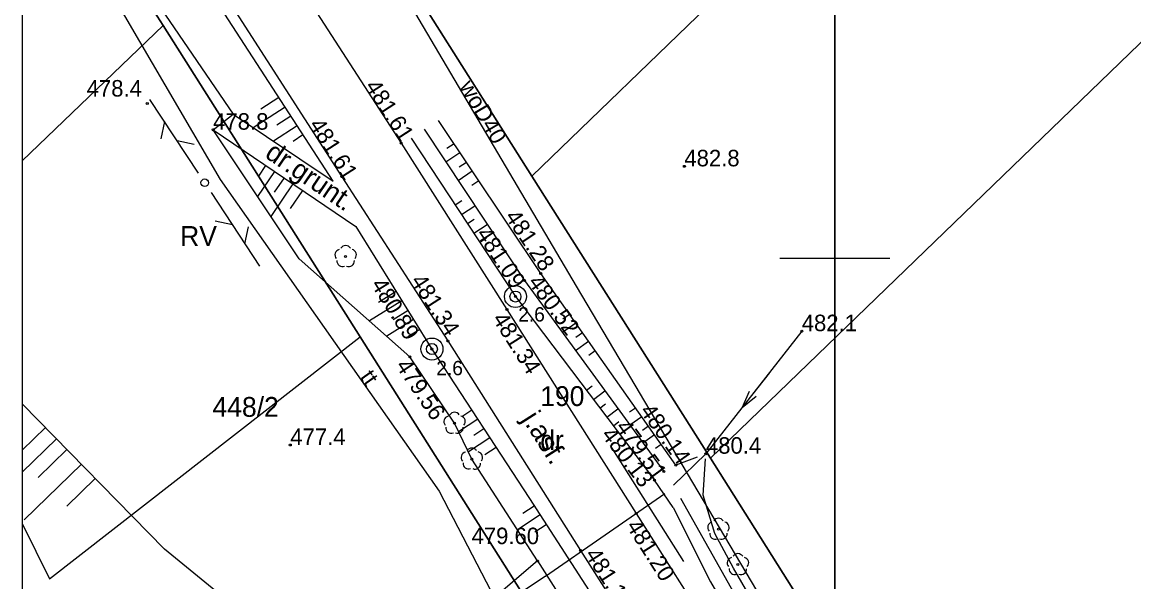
# Model space of a CAD drawing. Extents: x 4650326 to 4650741, y 5341000 to 5341288.
# Drawn here: x 4650326.2 to 4650427.1, y 5341070.6 to 5341121.4 of the extents above; entities that cross this region are included whole.
import ezdxf

# ---------------------------------------------------------------- set-up
doc = ezdxf.new("R2010")
doc.units = 0
for name, color, linetype in [('Warstwa 20', 7, 'Continuous'), ('Warstwa 24', 7, 'Continuous'), ('Warstwa 25', 7, 'Continuous'), ('Warstwa 26', 7, 'Continuous'), ('Warstwa 27', 7, 'Continuous'), ('Warstwa 35', 7, 'Continuous'), ('Warstwa 38', 7, 'Continuous'), ('Warstwa 41', 7, 'Continuous'), ('Warstwa 45', 7, 'Continuous'), ('Warstwa 46', 7, 'Continuous'), ('Warstwa 48', 7, 'Continuous'), ('Warstwa 50', 7, 'Continuous'), ('Warstwa 53', 7, 'Continuous'), ('Warstwa 60', 7, 'Continuous'), ('Warstwa 9', 7, 'Continuous')]:
    doc.layers.add(name, color=color, linetype=linetype)

msp = doc.modelspace()

# ---------------------------------------------------------------- linework, layer by layer
at = {"layer": 'Warstwa 20'}
msp.add_lwpolyline([(4650356.17, 5341132), (4650376.51, 5341097.46), (4650399.08, 5341059.32), (4650417.65, 5341028.07), (4650427.373, 5341012.003)], dxfattribs=at)
at = {"layer": 'Warstwa 25'}
for p, q in [((4650476.09, 5341207.62), (4650372.48, 5341107.47)), ((4650490.79, 5341180.52), (4650388.7, 5341081.84)), ((4650338.98, 5341121.15), (4650326.19, 5341141.38)), ((4650338.98, 5341121.15), (4650326.19, 5341141.38)), ((4650372.48, 5341107.47), (4650354.27, 5341136.26)), ((4650372.48, 5341107.47), (4650354.27, 5341136.26)), ((4650338.98, 5341121.15), (4650326.19, 5341108.843)), ((4650356.87, 5341092.87), (4650338.98, 5341121.15)), ((4650356.87, 5341092.87), (4650338.98, 5341121.15)), ((4650388.7, 5341081.84), (4650372.48, 5341107.47)), ((4650388.7, 5341081.84), (4650372.48, 5341107.47)), ((4650372.55, 5341068.08), (4650356.87, 5341092.87)), ((4650372.55, 5341068.08), (4650356.87, 5341092.87)), ((4650390.3, 5341079.3), (4650388.7, 5341081.84)), ((4650390.3, 5341079.3), (4650388.7, 5341081.84)), ((4650406.56, 5341053.51), (4650390.3, 5341079.3)), ((4650406.56, 5341053.51), (4650390.3, 5341079.3))]:
    msp.add_line(p, q, dxfattribs=at)
msp.add_lwpolyline([(4650326.19, 5341136.061), (4650331.83, 5341128.32), (4650344.18, 5341107.15), (4650364.07, 5341078.82), (4650371.33, 5341064.82), (4650381.68, 5341051.41)], dxfattribs=at)
at = {"layer": 'Warstwa 27'}
for p, q in [((4650326.19, 5341141.38), (4650338.98, 5341121.15)), ((4650326.19, 5341141.38), (4650338.98, 5341121.15)), ((4650354.27, 5341136.26), (4650372.48, 5341107.47)), ((4650354.27, 5341136.26), (4650372.48, 5341107.47)), ((4650338.98, 5341121.15), (4650356.87, 5341092.87)), ((4650338.98, 5341121.15), (4650356.87, 5341092.87)), ((4650372.48, 5341107.47), (4650388.7, 5341081.84)), ((4650372.48, 5341107.47), (4650388.7, 5341081.84)), ((4650328.68, 5341070.86), (4650356.87, 5341092.87)), ((4650356.87, 5341092.87), (4650372.55, 5341068.08)), ((4650356.87, 5341092.87), (4650372.55, 5341068.08)), ((4650388.7, 5341081.84), (4650390.3, 5341079.3)), ((4650388.7, 5341081.84), (4650390.3, 5341079.3)), ((4650390.3, 5341079.3), (4650406.56, 5341053.51)), ((4650390.3, 5341079.3), (4650406.56, 5341053.51)), ((4650326.19, 5341075.895), (4650328.68, 5341070.86))]:
    msp.add_line(p, q, dxfattribs=at)
at = {"layer": 'Warstwa 35'}
for p, q in [((4650343.53, 5341111.68), (4650345.35, 5341113.08)), ((4650379.6, 5341082.97), (4650386.24, 5341072.45)), ((4650385.31, 5341077.34), (4650383.62, 5341079.83)), ((4650373.71, 5341071.11), (4650384.57, 5341078.62)), ((4650372.25, 5341078.17), (4650379.35, 5341067.21)), ((4650372.99, 5341072.49), (4650374.64, 5341069.94))]:
    msp.add_line(p, q, dxfattribs=at)
for points in [[(4650340.68, 5341141.28), (4650360.61, 5341110.45), (4650370.22, 5341095.34), (4650381.95, 5341076.81), (4650396.56, 5341053.79), (4650422.67, 5341012.73), (4650423.136, 5341012.003)], [(4650335.36, 5341138.28), (4650345.04, 5341123.21), (4650355.21, 5341107.41), (4650364.84, 5341092.48), (4650376.91, 5341073.44), (4650391.69, 5341050.19), (4650398.26, 5341039.76), (4650401.18, 5341035.09), (4650415.921, 5341012.003)], [(4650354.42, 5341106.99), (4650344.2, 5341122.78), (4650334.38, 5341137.96)]]:
    msp.add_lwpolyline(points, dxfattribs=at)
for centre, radius in [((4650370.99, 5341096.52), 1), ((4650370.99, 5341096.52), 0.5), ((4650363.4, 5341091.75), 1), ((4650363.4, 5341091.75), 0.5)]:
    msp.add_circle(centre, radius, dxfattribs=at)
at = {"layer": 'Warstwa 38'}
msp.add_circle((4650342.77, 5341106.86), 0.35, dxfattribs=at)
at = {"layer": 'Warstwa 41'}
for centre in [(4650355.56, 5341100.15), (4650365.45, 5341085.01), (4650367.02, 5341081.75), (4650389.42, 5341075.38), (4650391.19, 5341072.16)]:
    msp.add_circle(centre, 0.09, dxfattribs=at)
for centre, start, end in [((4650355.567, 5341100.65), 30.76957, 149.23063), ((4650355.091, 5341100.302), 103.05194, 221.33515), ((4650356.042, 5341100.307), 318.93901, 77.55513), ((4650355.268, 5341099.749), 174.17267, 292.61566), ((4650355.856, 5341099.742), 246.13103, 4.5225), ((4650365.457, 5341085.51), 30.76957, 149.23063), ((4650364.981, 5341085.162), 103.05194, 221.33515), ((4650365.158, 5341084.609), 174.17267, 292.61566), ((4650365.932, 5341085.167), 318.93901, 77.55513), ((4650365.746, 5341084.602), 246.13103, 4.5225), ((4650367.027, 5341082.25), 30.76957, 149.23063), ((4650366.551, 5341081.902), 103.05194, 221.33515), ((4650367.502, 5341081.907), 318.93901, 77.55513), ((4650366.728, 5341081.349), 174.17267, 292.61566), ((4650367.316, 5341081.342), 246.13103, 4.5225), ((4650388.951, 5341075.532), 103.05194, 221.33515), ((4650389.427, 5341075.88), 30.76957, 149.23063), ((4650389.902, 5341075.537), 318.93901, 77.55513), ((4650389.128, 5341074.979), 174.17267, 292.61566), ((4650389.716, 5341074.972), 246.13103, 4.5225), ((4650390.721, 5341072.312), 103.05194, 221.33515), ((4650391.197, 5341072.66), 30.76957, 149.23063), ((4650391.672, 5341072.317), 318.93901, 77.55513), ((4650390.898, 5341071.759), 174.17267, 292.61566), ((4650391.486, 5341071.752), 246.13103, 4.5225)]:
    msp.add_arc(centre, 0.5, start, end, dxfattribs=at)
at = {"layer": 'Warstwa 45'}
for centre in [(4650337.55, 5341114.07), (4650343.53, 5341111.68), (4650360.61, 5341110.45), (4650386.33, 5341108.35), (4650355.21, 5341107.41), (4650371.8, 5341097.97), (4650373.28, 5341098.61), (4650370.99, 5341096.52), (4650370.22, 5341095.34), (4650396.99, 5341093.37), (4650363.4, 5341091.75), (4650364.84, 5341092.48), (4650361.4, 5341091.05), (4650350.54, 5341083.03), (4650388.29, 5341082.24), (4650384.47, 5341080.61), (4650385.56, 5341081.19), (4650383.62, 5341079.83), (4650381.95, 5341076.81), (4650372.99, 5341072.49), (4650376.91, 5341073.44)]:
    msp.add_circle(centre, 0.09, dxfattribs=at)
at = {"layer": 'Warstwa 46'}
for p, q in [((4650342.192, 5341107.737), (4650337.792, 5341114.418)), ((4650339.112, 5341112.414), (4650338.79, 5341110.847)), ((4650340.25, 5341110.686), (4650341.817, 5341110.363)), ((4650343.345, 5341105.982), (4650347.728, 5341099.289)), ((4650345.28, 5341103.028), (4650343.714, 5341103.354)), ((4650346.413, 5341101.297), (4650346.74, 5341102.862))]:
    msp.add_line(p, q, dxfattribs=at)
at = {"layer": 'Warstwa 48'}
for points in [[(4650326.19, 5341000.203), (4650737.19, 5341000.203), (4650737.19, 5341288.203), (4650326.19, 5341288.203)], [(4650326.19, 5341012.003), (4650737.19, 5341012.003), (4650737.19, 5341261.537), (4650326.19, 5341261.537)]]:
    msp.add_lwpolyline(points, close=True, dxfattribs=at)
at = {"layer": 'Warstwa 50'}
for p, q in [((4650349.49, 5341114.6), (4650347.86, 5341113.55)), ((4650350.06, 5341113.72), (4650347.18, 5341111.85)), ((4650351.16, 5341112.02), (4650349.01, 5341110.63)), ((4650350.59, 5341112.9), (4650349.33, 5341112.08)), ((4650351.69, 5341111.21), (4650350.79, 5341110.62)), ((4650365.41, 5341110.39), (4650364.77, 5341109.97)), ((4650365.95, 5341109.58), (4650364.68, 5341108.73)), ((4650349.11, 5341107.89), (4650347.56, 5341105.62)), ((4650348.3, 5341108.44), (4650347.64, 5341107.47)), ((4650367.07, 5341107.9), (4650365.8, 5341107.04)), ((4650366.53, 5341108.71), (4650365.89, 5341108.28)), ((4650349.97, 5341107.3), (4650349.08, 5341105.99)), ((4650367.66, 5341107.02), (4650367.02, 5341106.6)), ((4650350.78, 5341106.75), (4650348.77, 5341103.8)), ((4650351.65, 5341106.16), (4650350.52, 5341104.51)), ((4650365.51, 5341104.84), (4650366.12, 5341105.24)), ((4650366.09, 5341103.96), (4650367.31, 5341104.76)), ((4650366.63, 5341103.15), (4650367.23, 5341103.55)), ((4650367.2, 5341102.27), (4650368.42, 5341103.07)), ((4650367.74, 5341101.46), (4650368.35, 5341101.86)), ((4650360.16, 5341096.97), (4650358.56, 5341095.97)), ((4650360.67, 5341096.14), (4650357.72, 5341094.3)), ((4650361.23, 5341095.25), (4650359.88, 5341094.41)), ((4650375.91, 5341094.88), (4650375.3, 5341094.45)), ((4650361.74, 5341094.42), (4650359.3, 5341092.91)), ((4650376.47, 5341094.09), (4650375.26, 5341093.24)), ((4650362.29, 5341093.53), (4650361.21, 5341092.86)), ((4650377.07, 5341093.23), (4650376.48, 5341092.81)), ((4650377.63, 5341092.44), (4650376.45, 5341091.6)), ((4650378.24, 5341091.58), (4650377.65, 5341091.17)), ((4650377.44, 5341088), (4650377.97, 5341088.4)), ((4650378.07, 5341087.16), (4650379.11, 5341087.95)), ((4650378.66, 5341086.39), (4650379.17, 5341086.78)), ((4650367.03, 5341086.18), (4650366.21, 5341085.65)), ((4650379.29, 5341085.55), (4650380.3, 5341086.32)), ((4650381.9, 5341086.39), (4650381.35, 5341086)), ((4650367.56, 5341085.37), (4650365.82, 5341084.24)), ((4650379.88, 5341084.78), (4650380.38, 5341085.16)), ((4650382.46, 5341085.59), (4650381.38, 5341084.83)), ((4650383.06, 5341084.74), (4650382.53, 5341084.36)), ((4650328.31, 5341084.61), (4650326.19, 5341082.546)), ((4650368.66, 5341083.68), (4650366.71, 5341082.4)), ((4650368.13, 5341084.49), (4650367.21, 5341083.89)), ((4650383.62, 5341083.94), (4650382.57, 5341083.2)), ((4650329.3, 5341083.59), (4650326.19, 5341080.551)), ((4650369.23, 5341082.8), (4650368.22, 5341082.14)), ((4650384.22, 5341083.09), (4650383.7, 5341082.72)), ((4650330.25, 5341082.63), (4650327.63, 5341080.07)), ((4650331.56, 5341081.29), (4650326.37, 5341076.22)), ((4650332.81, 5341080), (4650330.24, 5341077.48)), ((4650373.22, 5341076.67), (4650371.16, 5341075.33)), ((4650372.7, 5341077.48), (4650371.67, 5341076.81)), ((4650373.79, 5341075.79), (4650372.76, 5341075.12))]:
    msp.add_line(p, q, dxfattribs=at)
for points in [[(4650326.19, 5341140.814), (4650334.23, 5341129.37), (4650345.35, 5341113.08), (4650354.42, 5341106.99)], [(4650387.49, 5341081.93), (4650385.56, 5341081.19), (4650373.28, 5341098.61), (4650363.99, 5341112.51)], [(4650343.53, 5341111.68), (4650356.48, 5341102.88), (4650363.4, 5341091.75), (4650372.25, 5341078.17)], [(4650372.99, 5341072.49), (4650367.02, 5341081.75), (4650365.45, 5341085.01), (4650361.4, 5341091.05), (4650351.34, 5341099.93), (4650343.53, 5341111.68)], [(4650362.69, 5341111.74), (4650371.8, 5341097.97), (4650384.47, 5341080.61)], [(4650361.52, 5341110.9), (4650370.99, 5341096.52), (4650383.62, 5341079.83)], [(4650372.99, 5341072.49), (4650368.82, 5341068.93), (4650361.34, 5341066.45), (4650355.07, 5341066.65), (4650350.09, 5341064.57), (4650339.1, 5341073.56), (4650326.19, 5341086.778)], [(4650406.82, 5341060.31), (4650400.86, 5341058.99), (4650397.53, 5341060.28), (4650390.8, 5341071.85), (4650389.11, 5341074.99), (4650388.04, 5341078.47), (4650388.26, 5341081.77)], [(4650407.19, 5341059.34), (4650400.92, 5341057.96), (4650396.57, 5341059.4), (4650386.02, 5341078.18)], [(4650385.31, 5341077.34), (4650388.71, 5341070.59), (4650395.77, 5341058.4), (4650400.94, 5341056.54), (4650407.35, 5341058.52)]]:
    msp.add_lwpolyline(points, dxfattribs=at)
at = {"layer": 'Warstwa 53'}
msp.add_line((4650373.71, 5341071.11), (4650369.41, 5341068.23), dxfattribs=at)
msp.add_lwpolyline([(4650396.99, 5341093.37), (4650388.29, 5341082.24), (4650385.35, 5341079.38)], dxfattribs=at)
at = {"layer": 'Warstwa 60'}
for p, q in [((4650400, 5341012.003), (4650400, 5341261.537)), ((4650400, 5341261.537), (4650400, 5341012.003)), ((4650400, 5341095), (4650400, 5341105)), ((4650400, 5341095), (4650400, 5341105)), ((4650400, 5341095), (4650400, 5341105)), ((4650395, 5341100), (4650400, 5341100)), ((4650395, 5341100), (4650405, 5341100)), ((4650400, 5341100), (4650405, 5341100))]:
    msp.add_line(p, q, dxfattribs=at)
at = {"layer": 'Warstwa 9'}
for p, q in [((4650394.02, 5341089.57), (4650392.548, 5341087.674)), ((4650391.567, 5341086.41), (4650392.232, 5341087.919)), ((4650392.864, 5341087.429), (4650391.567, 5341086.41))]:
    msp.add_line(p, q, dxfattribs=at)

# ---------------------------------------------------------------- texts
at = {"layer": 'Warstwa 20'}
msp.add_text('woD40', height=1.5, rotation=300.48745, dxfattribs=at).set_placement((4650365.82, 5341115.61))
at = {"layer": 'Warstwa 24'}
for s, p in [('190', (4650373.24, 5341086.57)), ('448/2', (4650343.47, 5341085.59))]:
    msp.add_text(s, height=1.8, dxfattribs=at).set_placement(p)
at = {"layer": 'Warstwa 25'}
msp.add_text('tt', height=1.5, rotation=305.07226, dxfattribs=at).set_placement((4650356.79, 5341089.19))
at = {"layer": 'Warstwa 26'}
for s, p in [('RV', (4650340.53, 5341101.12)), ('dr', (4650373.24, 5341082.57))]:
    msp.add_text(s, height=1.8, dxfattribs=at).set_placement(p)
at = {"layer": 'Warstwa 35'}
for s, rotation, p in [('dr.grunt.', 325.80244, (4650348.13, 5341109.23)), ('j.asf.', 302.37191, (4650371.54, 5341085.39))]:
    msp.add_text(s, height=1.8, rotation=rotation, dxfattribs=at).set_placement(p)
for p in [(4650371.24, 5341094.25), (4650363.8, 5341089.37)]:
    msp.add_text('2.6', height=1.3, dxfattribs=at).set_placement(p)
at = {"layer": 'Warstwa 45'}
for s, p in [('478.4', (4650332.04, 5341114.69)), ('478.8', (4650343.53, 5341111.68)), ('482.8', (4650386.33, 5341108.35)), ('482.1', (4650396.99, 5341093.37)), ('477.4', (4650350.54, 5341083.03)), ('480.4', (4650388.29, 5341082.24))]:
    msp.add_text(s, height=1.5, dxfattribs=at).set_placement(p)
at = {"layer": 'Warstwa 50'}
for s, rotation, p in [('481.61', 302.88069, (4650357.27, 5341115.62)), ('481.61', 302.76839, (4650352.18, 5341112.12)), ('481.28', 303.76419, (4650369.98, 5341103.78)), ('481.09', 303.36713, (4650367.37, 5341102.21)), ('480.89', 301.87114, (4650357.82, 5341097.62)), ('481.34', 302.82225, (4650361.43, 5341097.95)), ('480.52', 306.12363, (4650372.07, 5341097.81)), ('481.34', 302.33466, (4650368.84, 5341094.49)), ('479.56', 303.84326, (4650360.06, 5341090.23)), ('480.14', 305.18169, (4650382.24, 5341086.12)), ('479.51', 306.12363, (4650380.03, 5341084.65)), ('480.13', 307.116, (4650378.72, 5341083.94)), ('481.20', 302.4017, (4650381, 5341075.67)), ('481.18', 302.4441, (4650377.26, 5341073.09))]:
    msp.add_text(s, height=1.5, rotation=rotation, dxfattribs=at).set_placement(p)
msp.add_text('479.60', height=1.5, dxfattribs=at).set_placement((4650367, 5341074.02))

doc.saveas('drawing.dxf')
